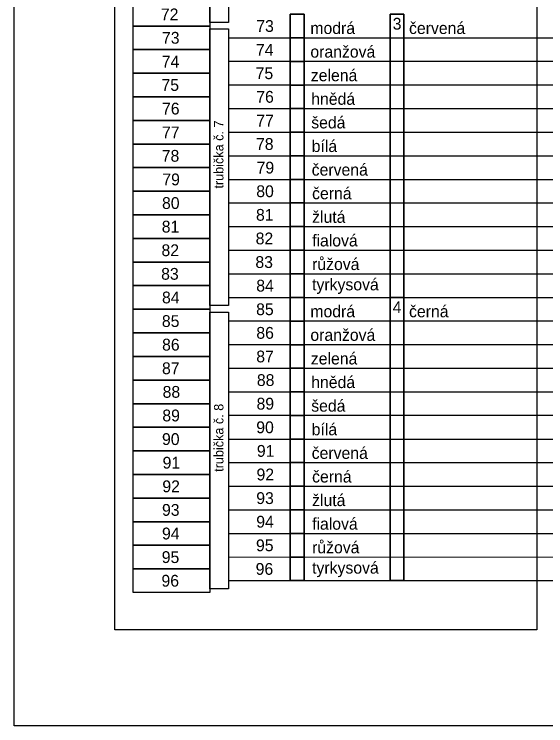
# Model space of a CAD drawing. Extents: x 1901 to 2519, y -3585 to -3154.
# Drawn here: x 1901.2 to 1980.5, y -3585 to -3478.9 of the extents above; entities that cross this region are included whole.
import ezdxf

# ---------------------------------------------------------------- set-up
doc = ezdxf.new("R2010")
doc.units = 0
doc.layers.add('rozvláknění', color=7, linetype='Continuous')
doc.layers.add('Vrstva 4', color=7, linetype='Continuous')

msp = doc.modelspace()

# ---------------------------------------------------------------- linework, layer by layer
at = {"layer": 'rozvláknění'}
for p, q in [((1930.39, -3482.38), (1930.41, -3482.38)), ((1933.19, -3482.36), (2025.9, -3482.36)), ((1930.39, -3485.9), (1930.41, -3485.9)), ((1933.19, -3485.88), (2025.9, -3485.88)), ((1930.39, -3489.42), (1930.41, -3489.42)), ((1933.19, -3489.4), (2025.9, -3489.4)), ((1933.19, -3489.42), (1933.19, -3492.94)), ((1930.39, -3492.94), (1930.41, -3492.94)), ((1933.19, -3492.94), (2025.9, -3492.94)), ((1930.39, -3496.46), (1930.41, -3496.46)), ((1933.19, -3496.46), (2025.9, -3496.46)), ((1930.39, -3499.98), (1930.41, -3499.98)), ((1933.19, -3499.97), (2025.9, -3499.98)), ((1933.19, -3499.98), (1933.19, -3503.5)), ((1930.39, -3503.5), (1930.41, -3503.5)), ((1933.19, -3503.49), (2025.9, -3503.49)), ((1930.39, -3507.02), (1930.41, -3507.02)), ((1933.19, -3507.01), (2025.9, -3507.01)), ((1930.39, -3510.54), (1930.41, -3510.54)), ((1933.19, -3510.53), (2025.9, -3510.53)), ((1933.19, -3510.54), (1933.19, -3514.06)), ((1930.39, -3514.06), (1930.41, -3514.06)), ((1933.19, -3514.05), (2025.9, -3514.05)), ((1930.39, -3517.58), (1930.41, -3517.58)), ((1933.19, -3517.56), (2025.9, -3517.57)), ((1930.39, -3521.1), (1930.41, -3521.1)), ((1933.19, -3521.08), (2025.9, -3521.08)), ((1930.39, -3524.62), (1930.41, -3524.62)), ((1933.19, -3524.6), (2025.9, -3524.6)), ((1930.39, -3528.14), (1930.41, -3528.14)), ((1933.19, -3528.12), (2025.9, -3528.12)), ((1930.39, -3531.66), (1930.41, -3531.66)), ((1933.19, -3531.64), (2025.9, -3531.64)), ((1933.19, -3531.66), (1933.19, -3535.18)), ((1930.39, -3535.18), (1930.41, -3535.18)), ((1933.19, -3535.16), (2025.9, -3535.16)), ((1930.39, -3538.7), (1930.41, -3538.7)), ((1933.19, -3538.67), (2025.9, -3538.68)), ((1930.39, -3542.22), (1930.41, -3542.22)), ((1933.19, -3542.21), (2025.9, -3542.22)), ((1933.19, -3542.22), (1933.19, -3545.74)), ((1930.39, -3545.74), (1930.41, -3545.74)), ((1933.19, -3545.73), (2025.9, -3545.73)), ((1930.39, -3549.26), (1930.41, -3549.26)), ((1933.19, -3549.25), (2025.9, -3549.25)), ((1930.39, -3552.78), (1930.41, -3552.78)), ((1933.19, -3552.77), (2025.9, -3552.77)), ((1933.19, -3552.78), (1933.19, -3556.3)), ((1930.39, -3556.3), (1930.41, -3556.3)), ((1933.19, -3556.29), (2025.9, -3556.29)), ((1930.39, -3559.82), (1930.41, -3559.82)), ((1933.19, -3559.8), (2025.9, -3559.81)), ((1930.39, -3563.34), (1930.41, -3563.34)), ((1933.19, -3563.32), (2025.9, -3563.32))]:
    msp.add_line(p, q, dxfattribs=at)
for points in [[(1916.21, -3379.28), (1979.2, -3379.28), (1979.2, -3570.66), (1916.21, -3570.66)], [(1930.41, -3438.82), (1933.19, -3438.82), (1933.19, -3480.08), (1930.41, -3480.08)], [(1918.95, -3477.1), (1930.39, -3477.1), (1930.39, -3480.62), (1918.95, -3480.62)], [(1942.4, -3478.87), (1944.45, -3478.87), (1944.45, -3482.38), (1942.4, -3482.38)], [(1959.32, -3521.08), (1957.28, -3521.08), (1957.28, -3478.87), (1959.32, -3478.87)], [(1918.95, -3480.62), (1930.39, -3480.62), (1930.39, -3484.14), (1918.95, -3484.14)], [(1930.41, -3481.06), (1933.19, -3481.06), (1933.19, -3522.32), (1930.41, -3522.32)], [(1942.4, -3482.38), (1944.45, -3482.38), (1944.45, -3485.9), (1942.4, -3485.9)], [(1918.95, -3484.14), (1930.39, -3484.14), (1930.39, -3487.66), (1918.95, -3487.66)], [(1942.4, -3485.9), (1944.45, -3485.9), (1944.45, -3489.42), (1942.4, -3489.42)], [(1918.95, -3487.66), (1930.39, -3487.66), (1930.39, -3491.18), (1918.95, -3491.18)], [(1942.4, -3489.42), (1944.45, -3489.42), (1944.45, -3492.94), (1942.4, -3492.94)], [(1918.95, -3491.18), (1930.39, -3491.18), (1930.39, -3494.7), (1918.95, -3494.7)], [(1942.4, -3492.94), (1944.45, -3492.94), (1944.45, -3496.46), (1942.4, -3496.46)], [(1918.95, -3494.7), (1930.39, -3494.7), (1930.39, -3498.22), (1918.95, -3498.22)], [(1942.4, -3496.46), (1944.45, -3496.46), (1944.45, -3499.98), (1942.4, -3499.98)], [(1918.95, -3498.22), (1930.39, -3498.22), (1930.39, -3501.74), (1918.95, -3501.74)], [(1942.4, -3499.98), (1944.45, -3499.98), (1944.45, -3503.49), (1942.4, -3503.49)], [(1918.95, -3501.74), (1930.39, -3501.74), (1930.39, -3505.26), (1918.95, -3505.26)], [(1942.4, -3503.49), (1944.45, -3503.49), (1944.45, -3507.01), (1942.4, -3507.01)], [(1918.95, -3505.26), (1930.39, -3505.26), (1930.39, -3508.78), (1918.95, -3508.78)], [(1942.4, -3507.01), (1944.45, -3507.01), (1944.45, -3510.53), (1942.4, -3510.53)], [(1918.95, -3508.78), (1930.39, -3508.78), (1930.39, -3512.3), (1918.95, -3512.3)], [(1942.4, -3510.53), (1944.45, -3510.53), (1944.45, -3514.05), (1942.4, -3514.05)], [(1918.95, -3512.3), (1930.39, -3512.3), (1930.39, -3515.82), (1918.95, -3515.82)], [(1942.4, -3514.05), (1944.45, -3514.05), (1944.45, -3517.57), (1942.4, -3517.57)], [(1918.95, -3515.82), (1930.39, -3515.82), (1930.39, -3519.34), (1918.95, -3519.34)], [(1942.4, -3517.57), (1944.45, -3517.57), (1944.45, -3521.08), (1942.4, -3521.08)], [(1918.95, -3519.34), (1930.39, -3519.34), (1930.39, -3522.86), (1918.95, -3522.86)], [(1942.4, -3521.11), (1944.45, -3521.11), (1944.45, -3524.62), (1942.4, -3524.62)], [(1959.32, -3563.32), (1957.28, -3563.32), (1957.28, -3521.11), (1959.32, -3521.11)], [(1918.95, -3522.86), (1930.39, -3522.86), (1930.39, -3526.38), (1918.95, -3526.38)], [(1930.41, -3523.3), (1933.19, -3523.3), (1933.19, -3564.56), (1930.41, -3564.56)], [(1942.4, -3524.62), (1944.45, -3524.62), (1944.45, -3528.14), (1942.4, -3528.14)], [(1918.95, -3526.38), (1930.39, -3526.38), (1930.39, -3529.9), (1918.95, -3529.9)], [(1942.4, -3528.14), (1944.45, -3528.14), (1944.45, -3531.66), (1942.4, -3531.66)], [(1918.95, -3529.9), (1930.39, -3529.9), (1930.39, -3533.42), (1918.95, -3533.42)], [(1942.4, -3531.66), (1944.45, -3531.66), (1944.45, -3535.18), (1942.4, -3535.18)], [(1918.95, -3533.42), (1930.39, -3533.42), (1930.39, -3536.94), (1918.95, -3536.94)], [(1942.4, -3535.18), (1944.45, -3535.18), (1944.45, -3538.7), (1942.4, -3538.7)], [(1918.95, -3536.94), (1930.39, -3536.94), (1930.39, -3540.46), (1918.95, -3540.46)], [(1942.4, -3538.7), (1944.45, -3538.7), (1944.45, -3542.22), (1942.4, -3542.22)], [(1918.95, -3540.46), (1930.39, -3540.46), (1930.39, -3543.98), (1918.95, -3543.98)], [(1942.4, -3542.22), (1944.45, -3542.22), (1944.45, -3545.73), (1942.4, -3545.73)], [(1918.95, -3543.98), (1930.39, -3543.98), (1930.39, -3547.5), (1918.95, -3547.5)], [(1942.4, -3545.73), (1944.45, -3545.73), (1944.45, -3549.25), (1942.4, -3549.25)], [(1918.95, -3547.5), (1930.39, -3547.5), (1930.39, -3551.02), (1918.95, -3551.02)], [(1942.4, -3549.25), (1944.45, -3549.25), (1944.45, -3552.77), (1942.4, -3552.77)], [(1918.95, -3551.02), (1930.39, -3551.02), (1930.39, -3554.54), (1918.95, -3554.54)], [(1942.4, -3552.77), (1944.45, -3552.77), (1944.45, -3556.29), (1942.4, -3556.29)], [(1918.95, -3554.54), (1930.39, -3554.54), (1930.39, -3558.06), (1918.95, -3558.06)], [(1942.4, -3556.29), (1944.45, -3556.29), (1944.45, -3559.81), (1942.4, -3559.81)], [(1918.95, -3558.06), (1930.39, -3558.06), (1930.39, -3561.58), (1918.95, -3561.58)], [(1942.4, -3559.81), (1944.45, -3559.81), (1944.45, -3563.32), (1942.4, -3563.32)], [(1918.95, -3561.58), (1930.39, -3561.58), (1930.39, -3565.1), (1918.95, -3565.1)]]:
    msp.add_lwpolyline(points, close=True, dxfattribs=at)
for points in [[(1942.4, -3482.38), (1944.45, -3482.38), (1944.45, -3478.87), (1942.4, -3478.87), (1942.4, -3482.38)], [(1959.32, -3478.87), (1957.28, -3478.87), (1957.28, -3521.08), (1959.32, -3521.08), (1959.32, -3478.87)], [(1959.32, -3478.87), (1957.28, -3478.87), (1957.28, -3521.08), (1959.32, -3521.08), (1959.32, -3478.87)], [(1959.32, -3478.87), (1957.28, -3478.87), (1957.28, -3521.08), (1959.32, -3521.08), (1959.32, -3478.87)], [(1959.32, -3478.87), (1957.28, -3478.87), (1957.28, -3521.08), (1959.32, -3521.08), (1959.32, -3478.87)], [(1959.32, -3478.87), (1957.28, -3478.87), (1957.28, -3521.08), (1959.32, -3521.08), (1959.32, -3478.87)], [(1942.4, -3485.9), (1944.45, -3485.9), (1944.45, -3482.38), (1942.4, -3482.38), (1942.4, -3485.9)], [(1942.4, -3489.42), (1944.45, -3489.42), (1944.45, -3485.9), (1942.4, -3485.9), (1942.4, -3489.42)], [(1942.4, -3492.94), (1944.45, -3492.94), (1944.45, -3489.42), (1942.4, -3489.42), (1942.4, -3492.94)], [(1942.4, -3496.46), (1944.45, -3496.46), (1944.45, -3492.94), (1942.4, -3492.94), (1942.4, -3496.46)], [(1942.4, -3499.98), (1944.45, -3499.98), (1944.45, -3496.46), (1942.4, -3496.46), (1942.4, -3499.98)], [(1942.4, -3503.49), (1944.45, -3503.49), (1944.45, -3499.98), (1942.4, -3499.98), (1942.4, -3503.49)], [(1942.4, -3507.01), (1944.45, -3507.01), (1944.45, -3503.49), (1942.4, -3503.49), (1942.4, -3507.01)], [(1942.4, -3510.53), (1944.45, -3510.53), (1944.45, -3507.01), (1942.4, -3507.01), (1942.4, -3510.53)], [(1942.4, -3514.05), (1944.45, -3514.05), (1944.45, -3510.53), (1942.4, -3510.53), (1942.4, -3514.05)], [(1942.4, -3517.57), (1944.45, -3517.57), (1944.45, -3514.05), (1942.4, -3514.05), (1942.4, -3517.57)], [(1942.4, -3521.08), (1944.45, -3521.08), (1944.45, -3517.57), (1942.4, -3517.57), (1942.4, -3521.08)], [(1942.4, -3524.62), (1944.45, -3524.62), (1944.45, -3521.11), (1942.4, -3521.11), (1942.4, -3524.62)], [(1959.32, -3521.11), (1957.28, -3521.11), (1957.28, -3563.32), (1959.32, -3563.32), (1959.32, -3521.11)], [(1959.32, -3521.11), (1957.28, -3521.11), (1957.28, -3563.32), (1959.32, -3563.32), (1959.32, -3521.11)], [(1959.32, -3521.11), (1957.28, -3521.11), (1957.28, -3563.32), (1959.32, -3563.32), (1959.32, -3521.11)], [(1959.32, -3521.11), (1957.28, -3521.11), (1957.28, -3563.32), (1959.32, -3563.32), (1959.32, -3521.11)], [(1959.32, -3521.11), (1957.28, -3521.11), (1957.28, -3563.32), (1959.32, -3563.32), (1959.32, -3521.11)], [(1942.4, -3528.14), (1944.45, -3528.14), (1944.45, -3524.62), (1942.4, -3524.62), (1942.4, -3528.14)], [(1942.4, -3531.66), (1944.45, -3531.66), (1944.45, -3528.14), (1942.4, -3528.14), (1942.4, -3531.66)], [(1942.4, -3535.18), (1944.45, -3535.18), (1944.45, -3531.66), (1942.4, -3531.66), (1942.4, -3535.18)], [(1942.4, -3538.7), (1944.45, -3538.7), (1944.45, -3535.18), (1942.4, -3535.18), (1942.4, -3538.7)], [(1942.4, -3542.22), (1944.45, -3542.22), (1944.45, -3538.7), (1942.4, -3538.7), (1942.4, -3542.22)], [(1942.4, -3545.73), (1944.45, -3545.73), (1944.45, -3542.22), (1942.4, -3542.22), (1942.4, -3545.73)], [(1942.4, -3549.25), (1944.45, -3549.25), (1944.45, -3545.73), (1942.4, -3545.73), (1942.4, -3549.25)], [(1942.4, -3552.77), (1944.45, -3552.77), (1944.45, -3549.25), (1942.4, -3549.25), (1942.4, -3552.77)], [(1942.4, -3556.29), (1944.45, -3556.29), (1944.45, -3552.77), (1942.4, -3552.77), (1942.4, -3556.29)], [(1942.4, -3559.81), (1944.45, -3559.81), (1944.45, -3556.29), (1942.4, -3556.29), (1942.4, -3559.81)], [(1942.4, -3563.32), (1944.45, -3563.32), (1944.45, -3559.81), (1942.4, -3559.81), (1942.4, -3563.32)]]:
    msp.add_lwpolyline(points, dxfattribs=at)
at = {"layer": 'Vrstva 4'}
msp.add_lwpolyline([(1901.22, -3154.47), (2516.22, -3154.47), (2516.22, -3584.97), (1901.22, -3584.97)], close=True, dxfattribs=at)

# ---------------------------------------------------------------- texts
at = {"layer": 'rozvláknění'}
for s, p in [('72', (1923.1, -3479.77)), ('73', (1937.33, -3481.5)), ('modrá', (1945.4, -3481.81)), ('3', (1957.68, -3481.16)), ('červená', (1960.12, -3481.81)), ('73', (1923.27, -3483.26)), ('74', (1937.29, -3485.05)), ('oranžová', (1945.4, -3485.33)), ('74', (1923.23, -3486.81)), ('75', (1937.24, -3488.54)), ('zelená', (1945.47, -3488.85)), ('75', (1923.19, -3490.3)), ('76', (1937.33, -3492.06)), ('hnědá', (1945.53, -3492.37)), ('76', (1923.27, -3493.82)), ('77', (1937.33, -3495.61)), ('šedá', (1945.53, -3495.89)), ('77', (1923.27, -3497.37)), ('78', (1937.29, -3499.1)), ('bílá', (1945.6, -3499.41)), ('78', (1923.23, -3500.86)), ('79', (1937.38, -3502.62)), ('červená', (1945.6, -3502.93)), ('79', (1923.32, -3504.38)), ('80', (1937.33, -3506.14)), ('černá', (1945.66, -3506.45)), ('80', (1923.27, -3507.9)), ('81', (1937.29, -3509.66)), ('žlutá', (1945.66, -3509.97)), ('81', (1923.23, -3511.42)), ('82', (1937.24, -3513.18)), ('fialová', (1945.66, -3513.49)), ('82', (1923.19, -3514.94)), ('83', (1937.2, -3516.7)), ('růžová', (1945.66, -3517.01)), ('83', (1923.14, -3518.46)), ('tyrkysová', (1945.66, -3520.04)), ('84', (1937.33, -3520.22)), ('84', (1923.27, -3521.98)), ('85', (1937.31, -3523.74)), ('modrá', (1945.4, -3524.05)), ('4', (1957.68, -3523.43)), ('černá', (1960.12, -3524.05)), ('85', (1923.25, -3525.5)), ('86', (1937.34, -3527.26)), ('oranžová', (1945.4, -3527.57)), ('86', (1923.28, -3529.02)), ('87', (1937.33, -3530.78)), ('zelená', (1945.47, -3531.09)), ('87', (1923.27, -3532.54)), ('88', (1937.42, -3534.3)), ('hnědá', (1945.53, -3534.61)), ('88', (1923.36, -3536.06)), ('89', (1937.37, -3537.82)), ('šedá', (1945.53, -3538.13)), ('89', (1923.32, -3539.58)), ('90', (1937.33, -3541.34)), ('bílá', (1945.6, -3541.65)), ('90', (1923.27, -3543.1)), ('91', (1937.42, -3544.86)), ('červená', (1945.6, -3545.17)), ('91', (1923.36, -3546.62)), ('92', (1937.37, -3548.38)), ('černá', (1945.66, -3548.69)), ('92', (1923.32, -3550.14)), ('93', (1937.33, -3551.9)), ('žlutá', (1945.66, -3552.21)), ('93', (1923.27, -3553.66)), ('94', (1937.33, -3555.42)), ('fialová', (1945.66, -3555.73)), ('94', (1923.27, -3557.18)), ('95', (1937.29, -3558.94)), ('růžová', (1945.66, -3559.25)), ('95', (1923.23, -3560.7)), ('96', (1937.24, -3562.46)), ('tyrkysová', (1945.66, -3562.28)), ('96', (1923.19, -3564.22))]:
    msp.add_text(s, height=1.76, dxfattribs=at).set_placement(p)
for s, p in [('trubička č. 7', (1932.43, -3504.86)), ('trubička č. 8', (1932.43, -3547.1))]:
    msp.add_text(s, height=1.408, rotation=90, dxfattribs=at).set_placement(p)

doc.saveas('drawing.dxf')
